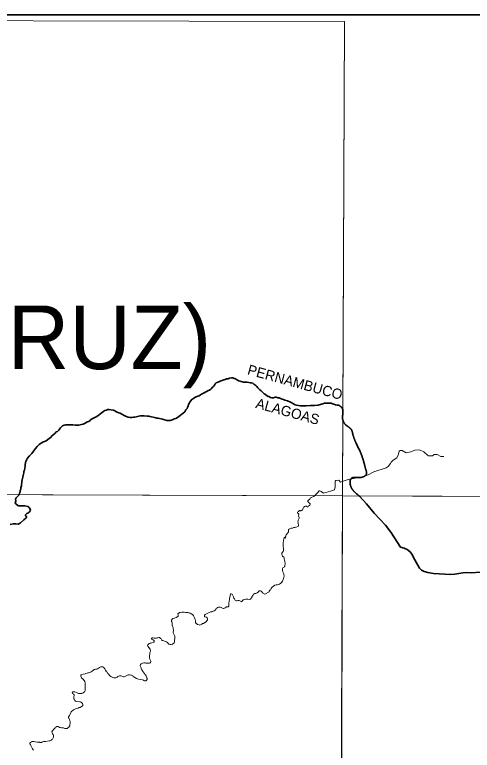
# Model space of a CAD drawing. Extents: x 553962 to 842807, y 8883888 to 9032388.
# Drawn here: x 594066 to 597659, y 8918990 to 8924770 of the extents above; entities that cross this region are included whole.
import ezdxf
from ezdxf.enums import TextEntityAlignment as Align

# ---------------------------------------------------------------- set-up
doc = ezdxf.new("R2010")
doc.units = 0
doc.header["$LTSCALE"] = 200
doc.linetypes.add('LONG_DASH_SHORT_DASH', pattern=[9.9, 6, -1.2, 1.5, -1.2])
doc.layers.add('6', color=7, linetype='Continuous', lineweight=13)

msp = doc.modelspace()

# ---------------------------------------------------------------- linework, layer by layer
at = {"layer": '6', "lineweight": 35}
msp.add_lwpolyline([(574695.3, 8924769.6), (626625.7, 8924769.6), (626625.7, 8896026.7), (574695.3, 8896026.7)], close=True, dxfattribs=at)
at = {"layer": '6'}
for points in [[(585656.3, 8924738.8), (596655.5, 8924715.8), (596639.8, 8920989.8), (585645.8, 8921027.3)], [(607600.8, 8920952.4), (596639.8, 8920989.8), (596608.8, 8909934.4), (607569.8, 8909894.9)]]:
    msp.add_lwpolyline(points, close=True, dxfattribs=at)
for points in [[(596655.5, 8924715.8), (596593.3, 8909930.3), (596531.7, 8896026.7)], [(597434.3, 8921299.7), (597411.5, 8921299.7), (597383.8, 8921313.7), (597360.5, 8921314.5), (597345.6, 8921303.6), (597314.4, 8921304.1), (597306.5, 8921308), (597277.6, 8921334.7), (597243.3, 8921349.7), (597206.9, 8921347.9), (597176.8, 8921335.1), (597140.6, 8921326.9), (597109.4, 8921345.3), (597091.8, 8921347), (597084, 8921340.9), (597080.4, 8921317.9), (597067.7, 8921289.1), (597038.2, 8921270.1), (597022.5, 8921254), (597017.6, 8921243.4), (596998.4, 8921219.3), (596982.5, 8921209.2), (596886.2, 8921177.5), (596841.4, 8921155.3), (596796, 8921139.4), (596684.4, 8921117.9), (596636.5, 8921101.1), (596623.7, 8921097.9), (596609.9, 8921111.7), (596587.7, 8921108.9), (596581.2, 8921103.5)], [(596581.2, 8921103.5), (596583.4, 8921058), (596577.4, 8921038.4), (596576.5, 8921036.9), (596546.9, 8921026.8), (596509.1, 8921016.7), (596491.7, 8921010.3), (596490, 8921010.8), (596472.1, 8921022.3), (596460.7, 8921029.2), (596459.6, 8921029.6), (596457.7, 8921028), (596445.2, 8921015.4), (596419.5, 8920988.9)], [(574684.9, 8921064.7), (596639.8, 8920989.8), (607636.3, 8920937.2), (626625.7, 8920820.5)], [(596419.5, 8920988.9), (596416.1, 8920985.5), (596411.6, 8920983.1), (596407.8, 8920981.7), (596399.5, 8920980), (596392.7, 8920976.5), (596389.8, 8920974.2), (596389.4, 8920973.2), (596388.5, 8920972.8), (596388, 8920971.8), (596387, 8920970.8), (596385.5, 8920968), (596383.2, 8920964.5), (596380.2, 8920960.7), (596376.2, 8920958.1), (596372.5, 8920956.2), (596369.6, 8920953.6), (596368.4, 8920952), (596367.4, 8920948.3), (596368.1, 8920946.1), (596368.2, 8920944.4), (596370, 8920941.5), (596371.9, 8920939.1), (596374.2, 8920937.3), (596377.3, 8920934.5), (596381, 8920931.9), (596384.8, 8920927.5), (596384.8, 8920927.5), (596385.6, 8920924.6), (596383.9, 8920916.4), (596383.6, 8920915.6), (596379.7, 8920913.5), (596373.2, 8920911.8), (596371.3, 8920906.5), (596370.2, 8920904.4), (596367.6, 8920903.1), (596364.1, 8920903.5), (596358.3, 8920907.2), (596357.3, 8920907.5), (596352.8, 8920907.7), (596347.5, 8920907.1), (596342.6, 8920904.7), (596337.1, 8920900), (596333.1, 8920895.9), (596322.9, 8920878.2)], [(596322.9, 8920878.2), (596321.8, 8920875.5), (596320.5, 8920873.2), (596315.8, 8920871.4), (596312.6, 8920871.3), (596310.4, 8920872.7), (596308.4, 8920874.5), (596303, 8920874.9), (596298.1, 8920868.6), (596293.7, 8920866.1), (596288.5, 8920862.6), (596287.3, 8920858.1), (596287.3, 8920855.8), (596289.2, 8920853.1), (596295.7, 8920846.8), (596296.2, 8920845.8), (596296.8, 8920842.9), (596295, 8920832), (596300.2, 8920819.4), (596299.3, 8920813.8), (596292.4, 8920797.3), (596290.7, 8920791.7), (596289.4, 8920786.3), (596290.7, 8920775), (596292.3, 8920769.4), (596293.4, 8920763.9), (596295.3, 8920758.3), (596294.3, 8920752.9), (596293.5, 8920751), (596289.7, 8920748.2), (596275.6, 8920744), (596269.9, 8920743.1), (596264.5, 8920741.9), (596258.8, 8920739.7), (596253.2, 8920738.4), (596247.6, 8920736.7), (596236.5, 8920735.2), (596230.9, 8920733.7), (596225.4, 8920731.3), (596218.8, 8920726.5), (596218.2, 8920725.5), (596216.7, 8920722.2), (596215.8, 8920715.7), (596215.7, 8920710.1), (596215.3, 8920707.1), (596211.6, 8920699.2), (596197.7, 8920682), (596193.8, 8920675.4), (596193.1, 8920667.7), (596194.2, 8920664.1), (596192.8, 8920660.7), (596192.2, 8920658.1), (596192, 8920658), (596185.8, 8920663.5), (596183.3, 8920663.3), (596181.1, 8920659.8), (596179.3, 8920654.3), (596178.1, 8920648.7), (596176.8, 8920637.8), (596175.7, 8920632), (596175.2, 8920626.1), (596173.4, 8920615.3), (596172.7, 8920609.8), (596172.8, 8920603.6), (596174.4, 8920586.9), (596175.3, 8920581.1), (596177.2, 8920575.1), (596177.8, 8920569.5), (596177.6, 8920563.3), (596177.3, 8920560), (596173.2, 8920551.4), (596169.7, 8920546), (596164.5, 8920539), (596163.8, 8920534.7), (596164.4, 8920529.3), (596165.8, 8920523.5), (596169.8, 8920515.6), (596179, 8920508.3), (596179.7, 8920507.3), (596181.2, 8920501.9), (596182.2, 8920495.7), (596184.6, 8920484.3), (596186.5, 8920477.5), (596189.9, 8920455.4)], [(596189.9, 8920455.4), (596189.5, 8920454.3), (596187.2, 8920440.2), (596187.2, 8920439.4), (596188.3, 8920437.7), (596188.3, 8920437.1), (596185.5, 8920433.8), (596181.5, 8920430.2), (596172.4, 8920423), (596169.5, 8920418.8), (596168.2, 8920412.8), (596168.7, 8920407.7), (596169.5, 8920402.7), (596172, 8920392.7), (596176.5, 8920381.4), (596178, 8920376.9), (596179.2, 8920371.6), (596180.6, 8920361.1), (596180.6, 8920356.3), (596179.6, 8920351.4), (596176.7, 8920340.8), (596168, 8920320.1), (596162.5, 8920310), (596158.8, 8920305.4), (596153.7, 8920300.7), (596148.8, 8920297.3), (596144, 8920294.9), (596139.2, 8920293.3), (596128.6, 8920290.9), (596118.2, 8920289.7), (596108.2, 8920286.6), (596097.6, 8920278.6)], [(596097.6, 8920278.6), (596087, 8920270.7), (596086.2, 8920270.4), (596080.9, 8920262.8), (596078.5, 8920257.9), (596076, 8920254.4), (596072.4, 8920250.1), (596065.8, 8920243.2), (596064.1, 8920240.6), (596063, 8920236.2), (596030, 8920216.7), (596014.6, 8920225.9), (596013.7, 8920226.2), (596013.1, 8920226.8), (596012.8, 8920227.7), (596010.9, 8920229.4), (596007.9, 8920232.8), (596000.2, 8920239.7), (595996.7, 8920242.2), (595992.4, 8920243.5), (595988.7, 8920243.2), (595985.4, 8920242.5), (595983.7, 8920241.8), (595981.6, 8920239.6), (595976.4, 8920232.6), (595973.2, 8920229.4), (595969.3, 8920226.3), (595963.4, 8920223.6), (595959.7, 8920222.4), (595955.7, 8920221.9), (595952, 8920221.1), (595948.5, 8920221.1), (595947.7, 8920220.8), (595944.7, 8920218.6), (595940.5, 8920213.8), (595940.1, 8920212.7), (595939.1, 8920212), (595936.7, 8920206.9)], [(595936.7, 8920206.9), (595936.6, 8920206.9), (595929.1, 8920195.6), (595929.2, 8920192.4), (595927.8, 8920190.1), (595924, 8920185.5), (595919.5, 8920180.9), (595916.5, 8920178.5), (595912.4, 8920177.2), (595907.3, 8920176.2), (595897.2, 8920177), (595891.9, 8920177.8), (595886.4, 8920177.8), (595881.6, 8920177.2), (595866.2, 8920173.5), (595861.1, 8920171.8), (595856.2, 8920168.8), (595848.9, 8920158.8), (595845, 8920158), (595843.1, 8920159.2), (595839.4, 8920163), (595833.5, 8920165.6), (595828.2, 8920166.5), (595818.6, 8920165.9), (595813.1, 8920165), (595806.4, 8920165.6), (595802.8, 8920167.3), (595797.3, 8920170.8), (595790.6, 8920180), (595786.8, 8920186.4), (595784.7, 8920191.3), (595784, 8920196.7), (595782.1, 8920201.6), (595779.5, 8920206.9), (595776.4, 8920211.9), (595772.8, 8920216), (595770, 8920218), (595764.9, 8920219.3), (595762.9, 8920219.2), (595760.1, 8920216.5), (595757.9, 8920212.1), (595756.5, 8920201.4), (595753, 8920186.6), (595752.3, 8920180.9), (595752.1, 8920171), (595750.8, 8920165.7), (595749.5, 8920155.6), (595748.2, 8920150.3), (595746.6, 8920135.4), (595747, 8920125.1), (595746.8, 8920123), (595744.1, 8920119), (595741.7, 8920117.9), (595733.7, 8920117.9), (595729, 8920117.3), (595726.8, 8920116.5), (595726.1, 8920116), (595719.5, 8920108.7), (595714.6, 8920105.7), (595709.3, 8920104.6), (595704.2, 8920104.7), (595697.4, 8920106.1), (595682.2, 8920114.9), (595680.4, 8920115.5), (595675.5, 8920115.9), (595665.3, 8920114.4), (595660.3, 8920112.3), (595658.1, 8920111)], [(595658.1, 8920111), (595655.6, 8920108.5), (595651.9, 8920104.2), (595647.8, 8920100.6), (595639.3, 8920091), (595632.7, 8920087), (595623.2, 8920082.6), (595617.5, 8920080.8), (595612.7, 8920078.9), (595606.8, 8920078.2), (595597.1, 8920075.8), (595591.6, 8920073.9), (595586.7, 8920071), (595581.7, 8920067.6), (595577.1, 8920064.8), (595571.5, 8920062.6), (595561.7, 8920056.4), (595561.7, 8920056.4), (595556.2, 8920051.1)], [(595556.2, 8920051.1), (595556.8, 8920041.8), (595557.1, 8920040.8), (595558.3, 8920039.9), (595568.7, 8920036.2), (595571.6, 8920035), (595576.8, 8920030.7), (595578.9, 8920025.4), (595579.7, 8920020.2), (595579.8, 8920016.6), (595579.2, 8920014.4), (595568.5, 8919999.7), (595567.3, 8919998.5), (595548.1, 8919986.8), (595541.1, 8919985.3), (595535.4, 8919982.4), (595524.6, 8919976), (595518.6, 8919974.3), (595513.3, 8919975), (595502.3, 8919979.2), (595495.2, 8919983.1), (595491.5, 8919987.2), (595486.8, 8919994.6), (595485.2, 8920000.2), (595484.5, 8920006.3), (595481.8, 8920018), (595479.4, 8920024.2), (595478.1, 8920030.1), (595476.1, 8920035.8), (595474.8, 8920037.4), (595472.3, 8920042.5), (595468.9, 8920048.1), (595462.9, 8920056.2), (595457.2, 8920059.5), (595444.2, 8920067.7), (595436.6, 8920069.9), (595431.2, 8920071), (595425.4, 8920071.8), (595413.3, 8920072.9), (595407.1, 8920073.8), (595395.5, 8920074.6), (595383.1, 8920075.9), (595377.1, 8920075.5), (595365.3, 8920073.2), (595359.7, 8920071.7), (595353.5, 8920068.5), (595349.8, 8920066.3), (595348.4, 8920064.4), (595347.6, 8920062.5), (595348.1, 8920060.6), (595350.5, 8920055.3), (595350.7, 8920050.2), (595349.1, 8920044.4), (595347.4, 8920041.8), (595332.8, 8920034.6), (595319.8, 8920029.3), (595308.8, 8920025.2), (595303.6, 8920020.4), (595296.8, 8920012.5), (595296.3, 8920010.1), (595296.8, 8920002), (595298.6, 8919998.5), (595301.1, 8919990.6), (595302.4, 8919978.8), (595303.5, 8919972.9), (595306.1, 8919966.4), (595309.8, 8919954.2), (595311.2, 8919942.8), (595312.2, 8919936.4), (595312.2, 8919930.6), (595310.5, 8919919.3), (595310.5, 8919914.1), (595312, 8919907.4), (595321.5, 8919891.2), (595322.7, 8919885.4), (595322.1, 8919874.5), (595322.3, 8919868.3), (595321.6, 8919856.8), (595320.8, 8919850.8), (595321, 8919844.9), (595319.8, 8919839.6), (595317.8, 8919835.8), (595315.7, 8919833.1), (595311, 8919828.8), (595304.7, 8919824.7), (595293.7, 8919822.5), (595287.7, 8919822.5), (595281.7, 8919822.9), (595279.6, 8919823.3), (595276.1, 8919825.3), (595270.4, 8919830.6), (595265.5, 8919837.5), (595259.1, 8919843.4), (595253.4, 8919845.2), (595241.8, 8919847.7), (595235.8, 8919849.4), (595229.3, 8919851.8), (595224.2, 8919853.9), (595221.7, 8919855.6), (595215.5, 8919865.8), (595211.5, 8919869.9)], [(595211.5, 8919869.9), (595211.5, 8919869.9), (595203.4, 8919875.3), (595196.7, 8919875.5), (595191.1, 8919874.5), (595185.1, 8919873.9), (595179.1, 8919872.2), (595173.5, 8919871.2), (595167, 8919870.5), (595163.5, 8919870.5), (595160.9, 8919871.1), (595149.3, 8919873), (595145.9, 8919872.6), (595141.2, 8919869.2), (595140.4, 8919866.2), (595140.9, 8919864.8), (595142, 8919862.9), (595154.1, 8919858.3), (595158.4, 8919853), (595159.9, 8919850), (595160.5, 8919846.3), (595160.3, 8919843.4), (595158.2, 8919840.8), (595152.4, 8919836.5), (595141.6, 8919833.3), (595135.4, 8919832.3), (595129.5, 8919831.1), (595122.5, 8919828.4), (595116, 8919824.6), (595113.1, 8919821.6), (595112.2, 8919820.4), (595109.5, 8919814.4), (595109.6, 8919812.9), (595111.6, 8919808.8), (595130.3, 8919784.6), (595131.4, 8919769.3), (595127.8, 8919758.5), (595126.5, 8919753.3), (595126, 8919748), (595123.7, 8919733.2), (595123.5, 8919727.1), (595123.7, 8919722.3), (595124.3, 8919717.4), (595126.6, 8919707.1), (595129.1, 8919701.7), (595132.3, 8919696.5), (595134.2, 8919691.2), (595134.9, 8919686.4), (595133.1, 8919680.8), (595132.3, 8919679.5), (595128.7, 8919677), (595125.3, 8919675.6), (595120.4, 8919674.8), (595115, 8919674.6), (595100.3, 8919676.1), (595094.8, 8919676.1), (595089.5, 8919676.5), (595084.5, 8919676.3), (595079.2, 8919676.5), (595069.2, 8919674.8), (595059.4, 8919670.2), (595055.8, 8919667.6), (595053.5, 8919663.7), (595052, 8919657.7), (595052.1, 8919654.1), (595055.6, 8919642.4), (595057.9, 8919637.1), (595059.3, 8919631.8), (595061.3, 8919625.8), (595063.1, 8919624.4), (595064.1, 8919622.7), (595069.5, 8919614.9), (595072.4, 8919609.9), (595076.3, 8919605.2), (595080.2, 8919598.6), (595084.2, 8919593.5), (595088.7, 8919586.8), (595092.6, 8919582.8), (595096.9, 8919576.3), (595099.5, 8919571.6), (595104.2, 8919560.8), (595105.8, 8919556), (595106, 8919550.3), (595104.9, 8919544.2), (595104.4, 8919543.4), (595101.4, 8919540.4), (595096.4, 8919537.1), (595091.3, 8919536.3), (595085.6, 8919536.5), (595079.3, 8919538.1), (595076.2, 8919540.5), (595069.8, 8919543.9), (595053.4, 8919547.8), (595038.5, 8919547.9)], [(595038.5, 8919547.9), (595038.5, 8919547.9), (595023.6, 8919553.8), (595021, 8919554), (594997.1, 8919569.7), (594992.7, 8919574.4), (594988.3, 8919577.5), (594983.2, 8919579.3), (594977.9, 8919580.7), (594967.4, 8919584.3), (594967.4, 8919584.3), (594962.5, 8919584), (594957.2, 8919582.7), (594952.2, 8919580.4), (594942.3, 8919574.2), (594931.7, 8919569.5), (594926.3, 8919568.6), (594921, 8919568.3), (594916.2, 8919569.5), (594900.8, 8919574.8), (594896.1, 8919576.2), (594890.9, 8919576.6), (594889, 8919576.3), (594880.2, 8919572.8), (594875.3, 8919569.6), (594870.1, 8919565.6), (594866.2, 8919563.1), (594861.2, 8919560.8), (594855.5, 8919559.2), (594850.6, 8919559), (594845, 8919559.4), (594835.2, 8919562.7), (594830.2, 8919564.8), (594824.9, 8919567.4), (594820.3, 8919570.2), (594811.4, 8919577.8), (594807, 8919583.8), (594798.1, 8919593.9), (594794.3, 8919597.8), (594791.6, 8919603.4), (594788, 8919608), (594780.1, 8919619.3), (594777, 8919624.9), (594773.5, 8919629.2), (594769.1, 8919635.6), (594765.6, 8919640.1), (594763.3, 8919642.3), (594758.6, 8919644.9), (594751.6, 8919646.6), (594748.7, 8919646.7), (594741, 8919644.8), (594731.3, 8919640.1), (594716.2, 8919630.9), (594710.7, 8919628.3), (594708.7, 8919627.7), (594700.3, 8919627), (594695.4, 8919625.8), (594690.4, 8919623.9), (594685.2, 8919620.5), (594675.3, 8919612.9), (594666.2, 8919607.6), (594660.5, 8919605.2), (594645.4, 8919599.5), (594640.1, 8919598), (594635, 8919595.8)], [(594635, 8919595.8), (594624.9, 8919592.5), (594619.4, 8919591.1), (594604.2, 8919588.8), (594593.8, 8919586.4), (594587.8, 8919584), (594585.7, 8919579.6), (594584.3, 8919574.8), (594584.1, 8919571.4), (594587.7, 8919564.4), (594590.8, 8919560), (594596.2, 8919553.6), (594605.1, 8919547.1), (594605.3, 8919546), (594606.5, 8919545.2), (594610.9, 8919538.4), (594616.3, 8919531.4), (594619.9, 8919521.3), (594620.2, 8919515.6), (594618.5, 8919500.2), (594620, 8919480), (594620.2, 8919469.6), (594619.8, 8919464.6), (594619, 8919459.8), (594616.9, 8919454.2), (594615.9, 8919452.5), (594614.8, 8919452.1), (594612.8, 8919449.7), (594607.4, 8919445.2), (594602.9, 8919441.7), (594598.5, 8919439.5), (594592.9, 8919437.8), (594578.2, 8919435.6), (594572.5, 8919436), (594567.4, 8919437), (594562.2, 8919439.2), (594557.3, 8919442)], [(594557.3, 8919442), (594551.1, 8919444.5), (594539.1, 8919448.8), (594529, 8919450.9), (594523.7, 8919450.9), (594521.8, 8919450.5), (594518.6, 8919448.1), (594517, 8919443.7), (594519, 8919439.4), (594520.5, 8919437), (594525.3, 8919433.8), (594525.3, 8919433.8), (594529.7, 8919430.2), (594531.2, 8919428.5), (594532.1, 8919425.1), (594532.7, 8919419.8), (594532.4, 8919417.8), (594530.1, 8919413.8), (594529.5, 8919408.7), (594529.5, 8919403), (594530.3, 8919397.9), (594531, 8919395.7), (594533, 8919392.5), (594535.7, 8919387.3), (594538.8, 8919382.7), (594543.6, 8919377), (594545.6, 8919375.7), (594551.1, 8919373.3), (594576.7, 8919371.7), (594582.3, 8919370.2), (594586.9, 8919367.9), (594591.9, 8919363.6), (594597, 8919358.8), (594601.1, 8919353.4), (594602, 8919350), (594601.8, 8919346.9), (594599.9, 8919341.8), (594598.6, 8919339), (594588.3, 8919331.5), (594580.2, 8919327.7), (594573.2, 8919325.4), (594563.1, 8919321), (594552.8, 8919318.4), (594542.7, 8919314.8), (594527.7, 8919307.4), (594522.1, 8919303.5), (594514.1, 8919296.6), (594510.3, 8919291.4), (594502.3, 8919274.3), (594499.6, 8919269.1), (594496.3, 8919263.8), (594489.6, 8919254.4), (594489, 8919253.2), (594488.6, 8919248.2), (594488.8, 8919245.4), (594490.3, 8919242.4), (594494, 8919237.2), (594496.5, 8919232.2), (594499.4, 8919222.1), (594500.3, 8919216.8), (594500.8, 8919206.3), (594500.1, 8919191.2), (594498.4, 8919183.1), (594497, 8919178.8), (594490.3, 8919171)], [(594490.3, 8919171), (594484.4, 8919165.8), (594480.2, 8919163.1), (594477.6, 8919161.8), (594469.8, 8919160.7), (594464.5, 8919161.2), (594459.5, 8919162.6), (594454.8, 8919164.9), (594447.9, 8919165.8), (594442.9, 8919167), (594432.3, 8919167.1), (594422.2, 8919168.6), (594417, 8919170.4), (594415.2, 8919171.5), (594414.2, 8919172.6), (594407, 8919176), (594402, 8919176.9), (594396.7, 8919176.5), (594395.1, 8919175.8), (594391.6, 8919175), (594386.4, 8919172.1), (594382.7, 8919167.2), (594378.2, 8919161.7), (594374, 8919155.7), (594365.4, 8919145.8), (594359, 8919139.7), (594358.8, 8919137.6), (594358.1, 8919135.4), (594358.9, 8919129.4), (594361.1, 8919124.1), (594364, 8919119.2), (594367.4, 8919114), (594369.6, 8919108.9), (594370.9, 8919103.1), (594371.3, 8919098.6), (594370.9, 8919093.8), (594370, 8919092.2)], [(594370, 8919092.2), (594368.7, 8919088), (594365.9, 8919083.2), (594362.2, 8919077.9), (594358.5, 8919074.3), (594356.6, 8919073), (594355.7, 8919072.7), (594354.9, 8919071.8), (594351.9, 8919070.4), (594346.7, 8919067.3), (594341.7, 8919065.7), (594336.4, 8919065.2), (594336.4, 8919065.2), (594306.8, 8919060.6), (594305.6, 8919059.7), (594301.6, 8919059.8), (594291, 8919058.2), (594282.8, 8919054.8), (594279.1, 8919053.6), (594275.2, 8919052.8), (594264, 8919052.8), (594259.8, 8919053.2), (594241.1, 8919053.8), (594225.3, 8919057.9), (594218.1, 8919058.5), (594210.2, 8919059.6), (594206.2, 8919059.4), (594202, 8919058.4), (594197, 8919057.8), (594190.4, 8919051.7), (594187.7, 8919049.6), (594185.5, 8919047.1), (594184.7, 8919043.1), (594185, 8919041.9), (594187.9, 8919036.1), (594190, 8919032.9), (594198.1, 8919016.4), (594199.7, 8919012.4), (594205.6, 8919001), (594211, 8918993.2), (594213.8, 8918990.1)]]:
    msp.add_lwpolyline(points, dxfattribs=at)
at = {"layer": '6', "linetype": 'LONG_DASH_SHORT_DASH', "lineweight": 35}
for points in [[(595503.7, 8921771.9), (595513.3, 8921776.4), (595523.8, 8921783.5), (595533.3, 8921787.6), (595542.8, 8921794.6), (595554.8, 8921799.7), (595565.9, 8921806.8), (595575.4, 8921810.3), (595584.9, 8921816.9), (595595.4, 8921821), (595607, 8921827), (595613.5, 8921834.6), (595619.5, 8921842.7), (595626.5, 8921849.7), (595635, 8921860.3), (595640.5, 8921868.3), (595647.9, 8921877.9), (595660, 8921882.5), (595669.5, 8921886.5), (595678, 8921891.1), (595709.1, 8921900.8), (595718.1, 8921904.3), (595730.2, 8921907.9), (595742.2, 8921908.9), (595753.8, 8921913), (595767.3, 8921916.1), (595779.9, 8921915.6), (595789.4, 8921912.7), (595799, 8921909.2), (595806.5, 8921903.2), (595816.6, 8921897.7), (595827.1, 8921893.8), (595861.3, 8921882.9), (595871.9, 8921882.9), (595892.5, 8921882), (595904, 8921881.1), (595916.1, 8921878.1), (595925.6, 8921877.1), (595934.7, 8921873.7), (595943.7, 8921867.2), (595952.3, 8921861.7), (595960.3, 8921855.2), (595968.4, 8921847.7), (595974, 8921838.7), (595983.5, 8921831.2), (595990.1, 8921821.7), (596000.2, 8921815.7), (596007.7, 8921809.2), (596016.8, 8921798.7), (596024.9, 8921790.7), (596035.4, 8921784.8), (596052.1, 8921771.8), (596061.6, 8921768.8), (596073.7, 8921763.3), (596085.2, 8921760.4), (596097.3, 8921760.4), (596110.3, 8921764.5), (596119.9, 8921763.6), (596131.4, 8921760.1), (596142.5, 8921759.1), (596153.6, 8921753.2), (596165.6, 8921749.7), (596176.7, 8921745.2), (596186.7, 8921741.8), (596208.8, 8921735.8), (596232, 8921724.4), (596241.6, 8921720.9), (596249.1, 8921714.9), (596268.7, 8921704.5), (596279.8, 8921701), (596294.3, 8921698.1), (596306.9, 8921697.1), (596320, 8921696.7), (596353.6, 8921696.8), (596389.2, 8921699), (596420.4, 8921700.1), (596448.5, 8921702.3), (596474.6, 8921709.4), (596486.1, 8921713.5), (596497.6, 8921717), (596508.2, 8921718.1), (596528.7, 8921718.2), (596538.8, 8921717.7), (596549.8, 8921716.3), (596560.4, 8921712.3), (596572.5, 8921708.8), (596585, 8921703.4), (596598.6, 8921701.4), (596611.6, 8921701.5)], [(594412.5, 8921504.4), (594417, 8921514), (594424.5, 8921525.1), (594441.5, 8921540.7), (594453.5, 8921543.8), (594464, 8921547.8), (594495.2, 8921548), (594509.2, 8921547.5), (594523.3, 8921547.6), (594543.9, 8921545.7), (594569, 8921545.8), (594580.6, 8921546.3), (594590.1, 8921549.9), (594603.7, 8921551.5), (594614.2, 8921558.1), (594625.2, 8921562.1), (594636.2, 8921569.7), (594646.8, 8921574.3), (594657.3, 8921581.8), (594664.3, 8921588.9), (594683.8, 8921599), (594696.4, 8921604.1), (594705.9, 8921609.2), (594718.4, 8921616.8), (594744.4, 8921639), (594765, 8921654.6), (594774, 8921659.2), (594786.5, 8921662.7), (594796.6, 8921666.8), (594808.1, 8921666.8), (594820.7, 8921664.4), (594841.3, 8921661.5), (594851.3, 8921657), (594860.9, 8921651), (594870.5, 8921647.1), (594883, 8921642.6), (594893.1, 8921638.6), (594925.8, 8921621.2), (594936.4, 8921614.7), (594958, 8921608.3), (594972.1, 8921605.8), (594986.1, 8921605.9), (594998.2, 8921606.4), (595010.2, 8921606.5), (595019.3, 8921610.1), (595029.8, 8921613.6), (595040.8, 8921614.7), (595049.9, 8921618.2), (595059.9, 8921618.8), (595070, 8921618.8), (595081.5, 8921618.4), (595106.1, 8921616.5), (595118.7, 8921616), (595128.2, 8921612.6), (595140.3, 8921610.1), (595153.9, 8921608.2), (595162.9, 8921604.7), (595173.5, 8921601.7), (595183, 8921600.8), (595193.1, 8921600.3), (595203.6, 8921596.8), (595217.2, 8921593.9), (595226.7, 8921592.9), (595259.9, 8921582), (595287, 8921582.1), (595309.1, 8921588.3), (595319.1, 8921594.3), (595331.2, 8921597.9), (595343.7, 8921605.5), (595354.2, 8921612.6), (595388.8, 8921638.3), (595402.3, 8921649.4), (595410.8, 8921664.5), (595419.2, 8921676.6), (595423.7, 8921686.2), (595427.2, 8921695.2), (595430.2, 8921707.8), (595437.2, 8921719.8), (595444.2, 8921729.4), (595460.7, 8921748.6), (595469.7, 8921754.1), (595481.2, 8921762.2), (595491.7, 8921767.8), (595503.7, 8921771.9)], [(594099.8, 8920996.9), (594100.5, 8921000.4), (594104, 8921009.5), (594109.4, 8921021.6), (594109.9, 8921032.1), (594113.9, 8921042.7), (594114.8, 8921055.2), (594118.3, 8921067.8), (594119.8, 8921079.9), (594121.7, 8921092.4), (594121.7, 8921102.5), (594125.7, 8921114.5), (594126.1, 8921125.6), (594130.1, 8921136.6), (594133.6, 8921148.2), (594134.5, 8921159.3), (594138, 8921170.8), (594138.5, 8921180.4), (594142.4, 8921191.4), (594146.8, 8921222.6), (594147.8, 8921236.1), (594153.7, 8921261.3), (594160.2, 8921273.3), (594164.2, 8921283.4), (594181.7, 8921304.6), (594199.2, 8921321.7), (594213.7, 8921339.4), (594222.2, 8921350.9), (594228.2, 8921360.5), (594241.7, 8921377.7), (594249.7, 8921386.2), (594257.7, 8921393.3), (594269.2, 8921400.9), (594278.7, 8921405.9), (594289.8, 8921413), (594300.8, 8921417.1), (594311.8, 8921422.1), (594322.3, 8921429.7), (594337.9, 8921443.3), (594348.4, 8921448.4), (594354.9, 8921457.5), (594365.9, 8921466.1), (594384.9, 8921482.7), (594392.4, 8921491.3), (594401.5, 8921496.3), (594412.5, 8921504.4)], [(594176.2, 8920899.4), (594168.7, 8920905.5), (594145.6, 8920910), (594098.9, 8920911.9), (594091.7, 8920913.9), (594073.9, 8920925.8), (594070.1, 8920934.3), (594074.3, 8920949.1), (594073.3, 8920964.4), (594077, 8920974.4), (594099.8, 8920996.9)], [(596772.7, 8920987.6), (596827.2, 8920927.7), (596887.6, 8920854.4), (596978.3, 8920759.7), (597020.1, 8920705.3), (597096.6, 8920585), (597125.2, 8920577.1), (597146.5, 8920568.5), (597170.2, 8920550.2), (597184.9, 8920530.7), (597208.4, 8920486.7), (597244.6, 8920421.2), (597260.6, 8920405.6), (597280.5, 8920395.7), (597310.8, 8920386.4), (597353.9, 8920380.3), (597487.5, 8920372), (597521, 8920374.3), (597585, 8920384.1), (597610.2, 8920386.4), (597650.2, 8920385.4), (597721.8, 8920389.3)], [(594030.9, 8920764), (594054.9, 8920770.3), (594073.9, 8920770.6), (594092, 8920768.1), (594103, 8920771.6), (594111.8, 8920776.3), (594138.2, 8920802.2), (594156.9, 8920817.3), (594159.3, 8920821.2), (594159, 8920825), (594150, 8920833.8), (594150.8, 8920840.9), (594161, 8920850.4), (594174.3, 8920856.6), (594180.7, 8920861.6), (594187.3, 8920871.1), (594189.3, 8920877.9), (594182.3, 8920894.6), (594176.2, 8920899.4)]]:
    msp.add_lwpolyline(points, dxfattribs=at)
msp.add_spline([(596611.2, 8921701.9), (596639.9, 8921673.2), (596639.9, 8921601.6), (596665.6, 8921547.2), (596711.4, 8921507.1), (596720, 8921478.5), (596734.3, 8921432.6), (596788.7, 8921312.3), (596811.6, 8921237.9), (596823.1, 8921194.9), (596828.8, 8921163.4), (596788.7, 8921134.8), (596705.7, 8921123.3), (596700, 8921083.2), (596772.7, 8920987.6)], degree=3, dxfattribs=at)

# ---------------------------------------------------------------- texts
at = {"layer": '6'}
msp.add_text('(POÇO DA CRUZ)', height=500, dxfattribs=at).set_placement((590036.9, 8921984.9))
for s, p in [('PERNAMBUCO', (596257.1, 8921844)), ('ALAGOAS', (596198.5, 8921614.1))]:
    msp.add_text(s, height=80, rotation=344.671, dxfattribs=at).set_placement(p, align=Align.CENTER)

doc.saveas('drawing.dxf')
